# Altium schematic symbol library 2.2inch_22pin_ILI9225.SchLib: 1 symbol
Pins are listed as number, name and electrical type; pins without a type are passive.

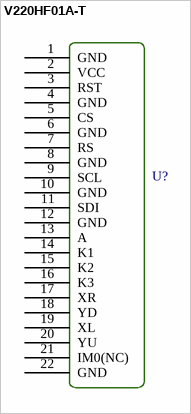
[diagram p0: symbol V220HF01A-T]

## V220HF01A-T
designator U?  (value not drawn)
pins: 1 GND, 2 VCC, 3 RST, 4 GND, 5 CS, 6 GND, 7 RS, 8 GND, 9 SCL, 10 GND, 11 SDI, 12 GND, 13 A, 14 K1, 15 K2, 16 K3, 17 XR, 18 YD, 19 XL, 20 YU, 21 IM0(NC), 22 GND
